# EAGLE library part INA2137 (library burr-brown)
Audio Differential Line Receivers +-6dB, G=1/2 or 2
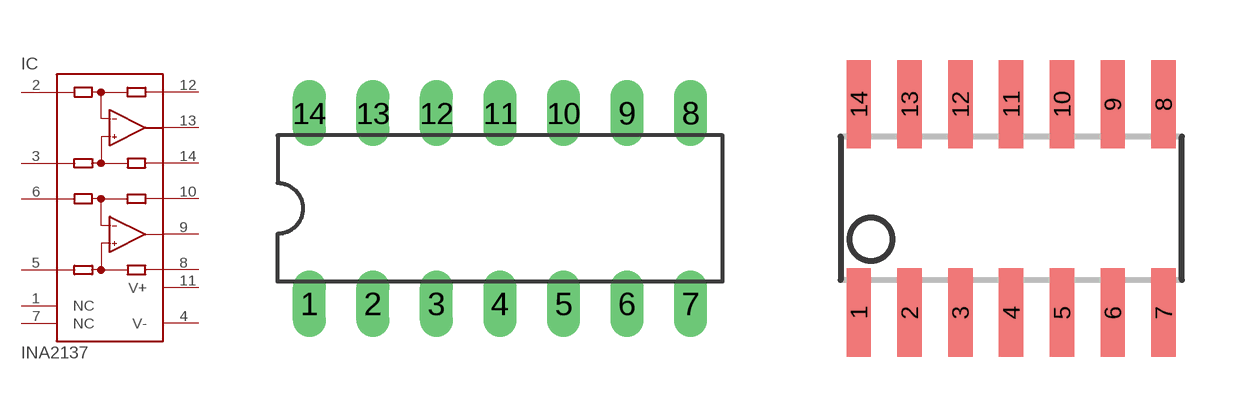
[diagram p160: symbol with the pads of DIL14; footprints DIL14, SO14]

Designator prefix IC

## INA2137P (MF: TEXAS INSTRUMENT CONNECTORS; MPN: INA2137PA; OC_FARNELL: unknown; OC_NEWARK: 18M9116)  [DIL14]
1  NC  nc
2  -INA  in
3  +INA  in
4  V-  pwr
5  +INB  in
6  -INB  in
7  NC  nc
8  REFB  pas
9  OUTB  out
10  SENSEB  pas
11  V+  pwr
12  SENSEA  pas
13  OUTA  out
14  REFA  pas

## INA2137U (MF: TEXAS INSTRUMENTS; MPN: INA2137UA; OC_FARNELL: 1703321; OC_NEWARK: 35C1749)  [SO14]
Pads as for DIL14

## Footprint DIL14 (pad centres in mm)
Dual In Line Package
drill 0.813 long: 1 -7.62,-3.81; 2 -5.08,-3.81; 3 -2.54,-3.81; 4 0,-3.81; 5 2.54,-3.81; 6 5.08,-3.81; 7 7.62,-3.81; 8 7.62,3.81; 9 5.08,3.81; 10 2.54,3.81; 11 0,3.81; 12 -2.54,3.81; 13 -5.08,3.81; 14 -7.62,3.81

## Footprint SO14 (pad centres in mm)
Small Outline Package
smd 0.61 x 2.21: 1 -3.81,-2.603; 2 -2.54,-2.603; 3 -1.27,-2.603; 4 0,-2.603; 5 1.27,-2.603; 6 2.54,-2.603; 7 3.81,-2.603; 8 3.81,2.603; 9 2.54,2.603; 10 1.27,2.603; 11 0,2.603; 12 -1.27,2.603; 13 -2.54,2.603; 14 -3.81,2.603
